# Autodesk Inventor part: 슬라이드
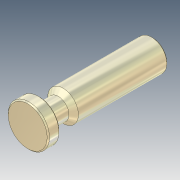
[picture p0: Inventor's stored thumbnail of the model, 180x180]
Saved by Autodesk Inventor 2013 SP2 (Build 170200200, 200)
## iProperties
Company: 한국ATC센터
Created: 2014-11
Part Number: 슬라이드
Document SubType Name: Modeling
Designer: KYOUNG IL JANG
Density: 7.86 g/cm^3
Material: 강, 연강
Mass: 436.103 g
Surface Area: 105.764 cm^2
Volume: 55.4838 cm^3
Author: KYOUNG IL JANG
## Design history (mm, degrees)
sketch "스케치1"
  geometry: L1 (19, 106.5)-(-19, 106.5) reference; L2 (0, 106.5)-(0, 212.5); L3 (0, 212.5)-(-13, 212.5); L4 (-13, 212.5)-(-13, 136.5); L5 (-9, 116.5)-(-17.5, 116.5); L6 (-17.5, 116.5)-(-17.5, 106.5); L7 (-17.5, 106.5)-(0, 106.5); L8 (-9, 116.5)-(-9, 132.5); L9 (-9, 132.5)-(-13, 136.5); 1 further point
  constraints: 18 end point, 3 perpendicular, 1 collinear, 1 horizontal, 1 midpoint, 1 parallel, 2 other
  dimensions: "d0" = 10 distance between parallel lines of L5 L7; "d1" = 35 diameter of L6 L2; "d2" = 106 distance of L2.start L2.end; "d3" = 135 deg angle of L9 L4; "d4" = 18 diameter of L8 L2; "d5" = 30 distance from line of L4.end L7; "d11" = 26 diameter of L4 L2
revolve "회전1" sketch "스케치1" stored, may be unused: angle "d6" = 90 deg
chamfer "모따기1" distance "d7" = 1; stored, may be unused: second distance "d8" = 2, angle "d9" = 45 deg
fillet "모깎기1" dims "d10" = 2
node "솔리드1"
